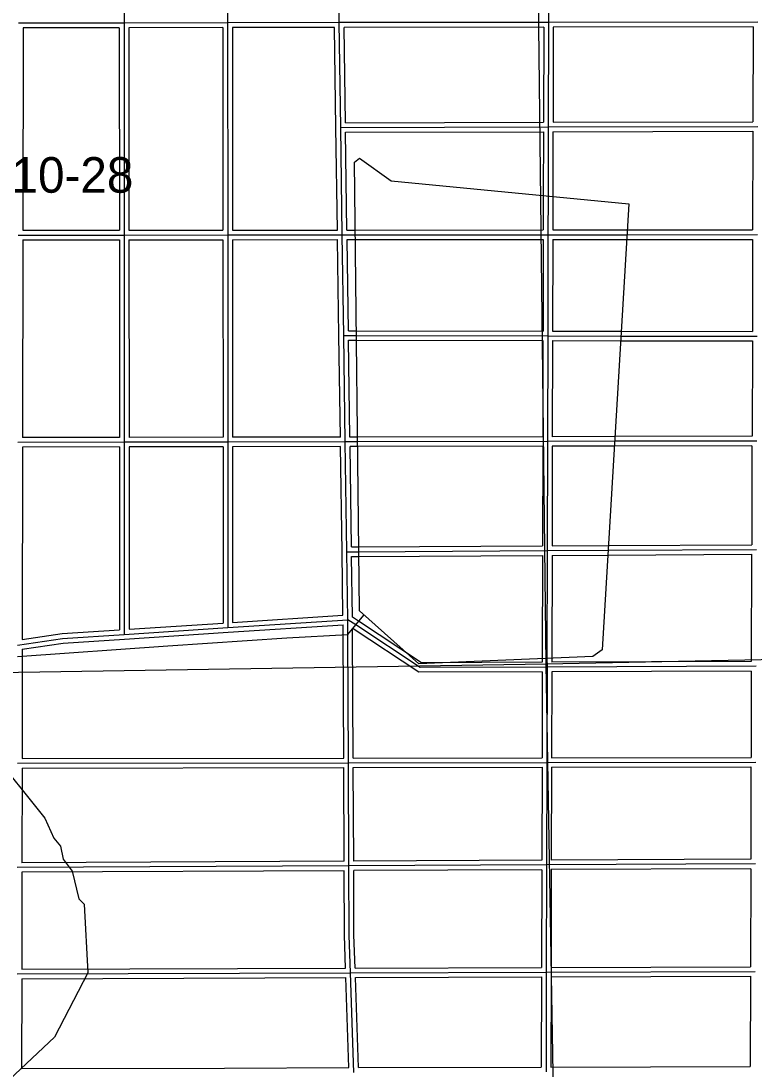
# Model space of a CAD drawing. Extents: x 418523 to 616617, y 1878279 to 2196743.
# Drawn here: x 512924 to 517554, y 1925999 to 1932620 of the extents above; entities that cross this region are included whole.
import ezdxf

# ---------------------------------------------------------------- set-up
doc = ezdxf.new("R2010")
doc.units = 0
for name, color, linetype in [('Level 1', 7, 'Continuous'), ('Level 2', 7, 'Continuous'), ('Level 31', 7, 'Continuous'), ('Level 32', 7, 'Continuous'), ('Level 5', 7, 'Continuous'), ('Level 7', 7, 'Continuous')]:
    doc.layers.add(name, color=color, linetype=linetype)

msp = doc.modelspace()

# ---------------------------------------------------------------- linework, layer by layer
at = {"layer": 'Level 1'}
for p, q in [((516240.655, 1928555.995), (516178.375, 1933906.316)), ((521625.505, 1928668.759), (516240.655, 1928555.995)), ((516240.655, 1928555.995), (510940.083, 1928474.48)), ((516322.072, 1923919.096), (516240.655, 1928555.995))]:
    msp.add_line(p, q, dxfattribs=at)
at = {"layer": 'Level 31'}
for p, q in [((513574.537, 1933839.997), (513575.179, 1932607.206)), ((514228.337, 1933856.021), (514228.944, 1932608.322)), ((514933.854, 1932609.618), (514924.558, 1933252.593)), ((516257.159, 1933254.789), (516255.359, 1932611.492)), ((513575.179, 1932607.206), (512908.071, 1932606.155)), ((514228.944, 1932608.322), (513575.179, 1932607.206)), ((513575.179, 1932607.206), (513576.045, 1931267.866)), ((514933.854, 1932609.618), (514228.944, 1932608.322)), ((514228.944, 1932608.322), (514229.514, 1931268.256)), ((516255.359, 1932611.492), (514933.854, 1932609.618)), ((514943.393, 1931947.368), (514933.854, 1932609.618)), ((516255.359, 1932611.492), (516254.125, 1931950.376)), ((517578.768, 1932613.408), (516255.359, 1932611.492)), ((514943.393, 1931947.368), (516254.125, 1931950.376)), ((514953.19, 1931268.752), (514943.393, 1931947.368)), ((516254.125, 1931950.376), (516252.794, 1931514.723)), ((516254.125, 1931950.376), (517576.929, 1931953.747)), ((516252.794, 1931514.723), (516252.5, 1931269.622)), ((512906.058, 1931267.551), (513576.045, 1931267.866)), ((513576.045, 1931267.866), (514229.514, 1931268.256)), ((513576.045, 1931267.866), (513576.712, 1929958.71)), ((514229.514, 1931268.256), (514953.19, 1931268.752)), ((514229.514, 1931268.256), (514230.206, 1929959.828)), ((514953.19, 1931268.752), (515036.421, 1931268.798)), ((514962.515, 1930633.415), (514953.19, 1931268.752)), ((515036.421, 1931268.798), (516252.5, 1931269.622)), ((516252.5, 1931269.622), (516251.035, 1930630.689)), ((516252.5, 1931269.622), (516746.175, 1931269.936)), ((516746.175, 1931269.936), (517575.001, 1931270.45)), ((514962.515, 1930633.415), (515041.618, 1930633.111)), ((514972.335, 1929960.981), (514962.515, 1930633.415)), ((515041.618, 1930633.111), (516251.035, 1930630.689)), ((516251.035, 1930630.689), (516249.461, 1929963.391)), ((516251.035, 1930630.689), (516709.767, 1930629.68)), ((516709.767, 1930629.68), (517573.228, 1930628.246)), ((513576.712, 1929958.71), (512904.156, 1929957.678)), ((514230.206, 1929959.828), (513576.712, 1929958.71)), ((513576.712, 1929958.71), (513576.794, 1928744.834)), ((514972.335, 1929960.981), (514230.206, 1929959.828)), ((514230.206, 1929959.828), (514230.47, 1928787.772)), ((515046.995, 1929961.423), (514972.335, 1929960.981)), ((514982.073, 1929266.731), (514972.335, 1929960.981)), ((516249.461, 1929963.391), (515046.995, 1929961.423)), ((516249.461, 1929963.391), (516248.12, 1929273.546)), ((516671.992, 1929964.337), (516249.461, 1929963.391)), ((517571.062, 1929966.041), (516671.992, 1929964.337)), ((514982.073, 1929266.731), (515052.285, 1929266.826)), ((514988.06, 1928837.596), (514982.073, 1929266.731)), ((515052.285, 1929266.826), (516248.12, 1929273.546)), ((516248.12, 1929273.546), (516246.192, 1928596.431)), ((516248.12, 1929273.546), (516632.54, 1929275.727)), ((516632.54, 1929275.727), (517568.81, 1929280.928)), ((514230.47, 1928787.772), (514988.06, 1928837.596)), ((514988.654, 1928743.771), (514988.06, 1928837.596)), ((515039.398, 1928803.944), (514988.06, 1928837.596)), ((513576.794, 1928744.834), (514230.47, 1928787.772)), ((515445.67, 1928535.836), (515039.398, 1928803.944)), ((514992.547, 1927933.174), (514988.654, 1928743.771)), ((516246.192, 1928596.431), (516246.29, 1928538.246)), ((516246.29, 1928538.246), (515445.67, 1928535.836)), ((516246.29, 1928538.246), (516244.959, 1927934.951)), ((517566.361, 1928543.086), (516246.29, 1928538.246)), ((512901.062, 1927929.958), (514992.547, 1927933.174)), ((514992.547, 1927933.174), (516244.959, 1927934.951)), ((514995.461, 1927281.861), (514992.547, 1927933.174)), ((516244.959, 1927934.951), (516243.463, 1927288.019)), ((516244.959, 1927934.951), (517564.725, 1927937.246)), ((514995.461, 1927281.861), (512900.1, 1927272.113)), ((516243.463, 1927288.019), (514995.461, 1927281.861)), ((516243.463, 1927288.019), (516241.852, 1926610.54)), ((517562.95, 1927294.315), (516243.463, 1927288.019)), ((512899.08, 1926598.995), (515005.272, 1926606.156)), ((515005.272, 1926606.156), (516241.852, 1926610.54)), ((515026.065, 1925977.321), (515005.272, 1926606.156)), ((516241.852, 1926610.54), (516240.102, 1925980.336)), ((516241.852, 1926610.54), (517561.04, 1926615.383))]:
    msp.add_line(p, q, dxfattribs=at)
for points in [[(512902.05, 1928676.535), (513187.194, 1928719.431), (513576.794, 1928744.834)], [(515005.272, 1926606.156), (514997.288, 1926845.106), (514995.461, 1927281.861)]]:
    msp.add_lwpolyline(points, dxfattribs=at)
at = {"layer": 'Level 32'}
for p, q in [((512938.028, 1932576.2), (512936.104, 1931297.566)), ((513545.199, 1932577.158), (512938.029, 1932576.201)), ((513545.199, 1932577.158), (513546.027, 1931297.852)), ((514198.956, 1932578.27), (513605.2, 1932577.256)), ((513605.2, 1932577.256), (513606.027, 1931297.884)), ((514198.957, 1932578.27), (514199.501, 1931298.238)), ((514904.284, 1932579.562), (514258.957, 1932578.376)), ((514258.957, 1932578.376), (514259.502, 1931298.276)), ((514913.396, 1931946.936), (514904.284, 1932579.562)), ((516225.303, 1932581.449), (514964.29, 1932579.66)), ((514972.965, 1931977.436), (514964.29, 1932579.659)), ((516225.303, 1932581.448), (516224.181, 1931980.306)), ((516285.304, 1932581.535), (516284.183, 1931980.452)), ((517548.685, 1932583.364), (516285.304, 1932581.535)), ((517548.685, 1932583.364), (517547.013, 1931983.672)), ((514922.754, 1931298.732), (514913.396, 1931946.936)), ((514972.965, 1931977.436), (516224.18, 1931980.306)), ((516284.183, 1931980.451), (517547.012, 1931983.671)), ((514973.83, 1931917.437), (516224.034, 1931920.305)), ((514982.761, 1931298.768), (514973.83, 1931917.436)), ((516224.034, 1931920.304), (516222.794, 1931514.815)), ((516284.035, 1931920.45), (516282.795, 1931514.631)), ((516284.035, 1931920.45), (517546.845, 1931923.67)), ((517546.845, 1931923.67), (517545.085, 1931300.431)), ((516222.794, 1931514.759), (516222.537, 1931299.601)), ((516282.795, 1931514.687), (516282.537, 1931299.641)), ((512936.105, 1931297.566), (513546.026, 1931297.851)), ((513606.027, 1931297.884), (514199.5, 1931298.237)), ((514259.502, 1931298.276), (514922.754, 1931298.731)), ((514982.76, 1931298.768), (515036.405, 1931298.797)), ((515036.402, 1931298.797), (516222.537, 1931299.601)), ((516282.538, 1931299.641), (516746.156, 1931299.936)), ((516746.157, 1931299.936), (517545.085, 1931300.431)), ((512936.016, 1931237.565), (512934.201, 1929987.724)), ((512936.016, 1931237.565), (513546.061, 1931237.851)), ((513546.061, 1931237.851), (513546.698, 1929988.664)), ((513606.062, 1931237.882), (513606.698, 1929988.761)), ((513606.063, 1931237.883), (514199.53, 1931238.237)), ((514199.53, 1931238.237), (514200.19, 1929989.776)), ((514259.53, 1931238.276), (514260.191, 1929989.875)), ((514259.531, 1931238.276), (514923.628, 1931238.731)), ((514932.518, 1930632.974), (514923.627, 1931238.731)), ((514983.635, 1931238.768), (515036.439, 1931238.797)), ((514992.081, 1930663.301), (514983.635, 1931238.767)), ((515036.442, 1931238.797), (516222.431, 1931239.6)), ((516222.432, 1931239.6), (516221.104, 1930660.749)), ((516282.432, 1931239.639), (516281.105, 1930660.622)), ((516282.433, 1931239.64), (516746.195, 1931239.936)), ((516746.194, 1931239.936), (517544.918, 1931240.431)), ((517544.919, 1931240.431), (517543.311, 1930658.296)), ((514941.895, 1929990.933), (514932.518, 1930632.976)), ((514992.081, 1930663.301), (515041.733, 1930663.111)), ((515041.678, 1930663.111), (516221.103, 1930660.748)), ((516281.105, 1930660.622), (516709.834, 1930659.68)), ((516709.818, 1930659.68), (517543.311, 1930658.296)), ((514992.96, 1930603.296), (515041.504, 1930603.111)), ((515001.9, 1929991.157), (514992.96, 1930603.296)), ((515041.559, 1930603.111), (516220.964, 1930600.747)), ((516220.964, 1930600.747), (516219.532, 1929993.341)), ((516280.965, 1930600.621), (516279.533, 1929993.457)), ((516280.965, 1930600.621), (516709.702, 1930599.679)), ((516709.718, 1930599.679), (517543.13, 1930598.295)), ((517543.13, 1930598.295), (517541.16, 1929995.985)), ((513546.698, 1929988.664), (512934.201, 1929987.723)), ((514200.19, 1929989.776), (513606.698, 1929988.761)), ((514941.895, 1929990.933), (514260.192, 1929989.874)), ((515046.818, 1929991.423), (515001.9, 1929991.156)), ((516219.531, 1929993.341), (515046.946, 1929991.423)), ((516671.925, 1929994.336), (516279.533, 1929993.457)), ((517541.16, 1929995.984), (516671.936, 1929994.336)), ((512934.109, 1929927.722), (512932.108, 1928711.394)), ((513546.715, 1929928.663), (512934.109, 1929927.722)), ((513546.715, 1929928.662), (513546.793, 1928772.942)), ((513606.715, 1929928.76), (513606.793, 1928776.869)), ((514200.214, 1929929.775), (513606.716, 1929928.761)), ((514200.214, 1929929.775), (514200.464, 1928815.866)), ((514942.755, 1929930.935), (514260.214, 1929929.873)), ((514260.214, 1929929.872), (514260.465, 1928819.809)), ((514952.076, 1929266.309), (514942.754, 1929930.934)), ((515047.173, 1929931.422), (515002.759, 1929931.16)), ((515011.657, 1929296.771), (515002.759, 1929931.16)), ((516219.403, 1929933.341), (515047.045, 1929931.422)), ((516219.404, 1929933.34), (516218.179, 1929303.378)), ((516279.404, 1929933.456), (516278.18, 1929303.717)), ((516672.06, 1929934.336), (516279.405, 1929933.456)), ((517540.963, 1929935.982), (516672.05, 1929934.336)), ((517540.964, 1929935.982), (517538.909, 1929310.761)), ((515011.656, 1929296.77), (515052.245, 1929296.826)), ((515052.117, 1929296.826), (516218.179, 1929303.378)), ((516278.18, 1929303.717), (516632.37, 1929305.727)), ((516632.374, 1929305.727), (517538.909, 1929310.762)), ((514957.665, 1928865.662), (514952.076, 1929266.311)), ((515017.835, 1928853.949), (515012.495, 1929236.77)), ((515012.496, 1929236.77), (515052.326, 1929236.825)), ((515052.454, 1929236.825), (516218.034, 1929243.375)), ((516218.034, 1929243.375), (516216.192, 1928596.516)), ((516278.036, 1929243.713), (516276.192, 1928596.345)), ((516278.036, 1929243.714), (516632.711, 1929245.726)), ((516632.708, 1929245.726), (517538.71, 1929250.758)), ((517538.71, 1929250.759), (517536.461, 1928572.976)), ((514260.465, 1928819.809), (514957.665, 1928865.662)), ((515055.845, 1928829.034), (515017.835, 1928853.949)), ((513606.793, 1928776.87), (514200.464, 1928815.866)), ((514232.44, 1928757.836), (514958.262, 1928805.571)), ((514958.654, 1928743.581), (514958.262, 1928805.571)), ((515018.655, 1928743.961), (515018.415, 1928781.826)), ((515022.874, 1928778.904), (515018.415, 1928781.826)), ((515436.705, 1928505.807), (515022.874, 1928778.904)), ((515454.635, 1928565.862), (515055.923, 1928828.983)), ((513578.761, 1928714.898), (514232.437, 1928757.836)), ((514962.404, 1927963.127), (514958.654, 1928743.627)), ((515022.405, 1927963.216), (515018.655, 1928743.916)), ((512932.064, 1928650.711), (512932.087, 1928604.181)), ((512932.087, 1928604.121), (512931.109, 1927960.004)), ((516216.24, 1928568.156), (515454.636, 1928565.862)), ((516216.192, 1928596.381), (516216.24, 1928568.156)), ((516276.192, 1928596.345), (516276.24, 1928568.356)), ((517536.461, 1928572.976), (516276.24, 1928568.356)), ((516216.223, 1928508.155), (515436.704, 1928505.807)), ((516216.224, 1928508.155), (516215.025, 1927964.91)), ((516276.225, 1928508.355), (516275.026, 1927965.003)), ((517536.28, 1928512.973), (516276.225, 1928508.355)), ((517536.28, 1928512.973), (517534.806, 1927967.194)), ((512931.019, 1927900.003), (514962.681, 1927903.126)), ((512931.11, 1927960.004), (514962.404, 1927963.126)), ((514965.328, 1927311.721), (514962.681, 1927903.126)), ((515022.405, 1927963.216), (516215.025, 1927964.909)), ((515022.683, 1927903.215), (516214.889, 1927904.908)), ((515025.328, 1927312.008), (515022.683, 1927903.215)), ((516214.889, 1927904.907), (516213.533, 1927317.871)), ((516274.89, 1927905.002), (516273.534, 1927318.162)), ((516274.891, 1927905.002), (517534.643, 1927907.193)), ((516275.026, 1927965.003), (517534.805, 1927967.194)), ((517534.643, 1927907.193), (517533.033, 1927324.172)), ((512931.019, 1927900.003), (512930.145, 1927302.252)), ((514965.328, 1927311.721), (512930.146, 1927302.253)), ((516213.532, 1927317.871), (515025.328, 1927312.008)), ((517533.032, 1927324.171), (516273.534, 1927318.162)), ((512930.056, 1927242.25), (512929.127, 1926629.096)), ((514965.587, 1927251.719), (512930.056, 1927242.25)), ((516213.392, 1927257.869), (515025.589, 1927252.007)), ((516213.392, 1927257.869), (516211.923, 1926640.434)), ((516273.394, 1927258.16), (516271.925, 1926640.65)), ((517532.865, 1927264.169), (516273.394, 1927258.161)), ((517532.865, 1927264.168), (517531.125, 1926645.273)), ((516271.925, 1926640.65), (517531.125, 1926645.273)), ((512929.128, 1926629.096), (514974.256, 1926636.05)), ((515034.284, 1926636.258), (516211.923, 1926640.433)), ((515036.278, 1926576.263), (516211.768, 1926580.432)), ((516211.768, 1926580.431), (516210.186, 1926010.261)), ((516271.77, 1926580.648), (516270.187, 1926010.414)), ((516271.77, 1926580.648), (517530.942, 1926585.271)), ((517530.942, 1926585.271), (517529.086, 1926013.649)), ((512929.027, 1926569.094), (512927.977, 1926001.773)), ((512929.027, 1926569.095), (514976.251, 1926576.055)), ((514995.059, 1926007.231), (514976.251, 1926576.054)), ((515055.088, 1926007.393), (515036.278, 1926576.264)), ((512927.977, 1926001.773), (514209.11, 1926004.997)), ((514209.1, 1926004.997), (514995.06, 1926007.231)), ((515055.089, 1926007.392), (516210.186, 1926010.261)), ((516270.187, 1926010.413), (517529.086, 1926013.649))]:
    msp.add_line(p, q, dxfattribs=at)
for points in [[(512932.108, 1928711.394), (513183.98, 1928749.286), (513546.793, 1928772.941)], [(512932.065, 1928650.711), (513190.407, 1928689.576), (513578.746, 1928714.897)], [(514974.256, 1926636.05), (514967.29, 1926844.542), (514965.588, 1927251.72)], [(515034.284, 1926636.258), (515027.286, 1926845.67), (515025.588, 1927252.006)]]:
    msp.add_lwpolyline(points, dxfattribs=at)
at = {"layer": 'Level 5'}
for p, q in [((515039.398, 1928803.944), (515090.465, 1928865.57)), ((514988.654, 1928743.771), (515039.398, 1928803.944))]:
    msp.add_line(p, q, dxfattribs=at)
msp.add_lwpolyline([(515436.19, 1928559.056), (515062.126, 1928893.69), (515029.515, 1931728.185), (515062.966, 1931753.096), (515262.583, 1931610.716), (516762.667, 1931464.201), (516595.233, 1928647.034), (516536.743, 1928605.542), (515436.19, 1928559.056)], close=True, dxfattribs=at)
msp.add_lwpolyline([(512902.086, 1928604.167), (513850.695, 1928673.229), (514602.887, 1928723.43), (514988.654, 1928743.771)], dxfattribs=at)
at = {"layer": 'Level 7'}
msp.add_lwpolyline([(512725.113, 1928017.559), (513073.869, 1927582.923), (513131.802, 1927457.711), (513173.314, 1927407.561), (513189.725, 1927324.129), (513247.858, 1927248.907), (513288.982, 1927073.714), (513322.193, 1927040.274), (513345.831, 1926606.684), (513136.125, 1926198.891), (512851.803, 1925933.041)], dxfattribs=at)

# ---------------------------------------------------------------- texts
at = {"layer": 'Level 2'}
msp.add_text('11-10-28', height=225, dxfattribs=at).set_placement((512429.527, 1931534.953))

doc.saveas('drawing.dxf')
